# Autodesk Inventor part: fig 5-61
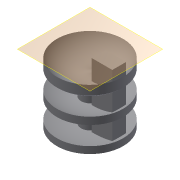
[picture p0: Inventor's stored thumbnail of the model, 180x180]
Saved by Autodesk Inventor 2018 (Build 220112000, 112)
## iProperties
Created: 2004-05
Part Number: fig 5-61
Document SubType Name: Modeling
Designer: CADCIM Technologies
Manufacturer: Standard
Standards Organization: Custom
Density: 1 g/cm^3
Material: Generic
Appearance: Default
Author: CADCIM Technologies
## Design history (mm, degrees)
sketch "Sketch1"
  geometry: L1 (0.098, 22.743)-(0.098, 0.516); L2 (-3.621, 19.305)-(-3.621, 13.061); L3 (-3.621, 10.379)-(-3.621, 3.25); L4 (-3.664, 0.516)-(0.098, 0.516); L5 (-13.694, 4.7)-(-13.694, 1.836); L6 (-13.694, 26.851)-(-13.694, 23.014); L7 (-13.694, 15.335)-(-13.694, 12.343); A1 r 10.546 centre (-4.597, 32.185) between (-13.694, 26.851) and (0.098, 22.743); A2 r 21.828 centre (-4.597, 32.185) between (-13.694, 12.343) and (-3.621, 10.379); A3 r 12.918 centre (-4.597, 32.185) between (-13.694, 23.014) and (-3.621, 19.305); A4 r 19.149 centre (-4.597, 32.185) between (-13.694, 15.335) and (-3.621, 13.061); A5 r 28.952 centre (-4.597, 32.185) between (-13.694, 4.7) and (-3.621, 3.25); A6 r 31.683 centre (-4.597, 32.185) between (-13.694, 1.836) and (-3.664, 0.516)
  constraints: 14 end point, 12 point on circle, 6 centre point, 4 perpendicular, 2 parallel, 1 vertical
revolve "Revolution1" sketch "Sketch1" stored, may be unused: angle "d0" = 90 deg
workplane "Work Plane1"
sketch "Sketch2"
  geometry: L1 (3.408, -2.846)-(12.06, -2.846); L2 (12.06, -2.846)-(12.06, 2.873); L3 (12.06, 2.873)-(3.408, 2.873); L4 (3.408, 2.873)-(3.408, -2.846)
  constraints: 8 end point, 2 parallel, 1 horizontal, 1 perpendicular
extrude "Extrusion3" join sketch "Sketch2" extent not by distance; stored distance "d8" = 10; taper "d9" = 0 deg
body "Solid1"
